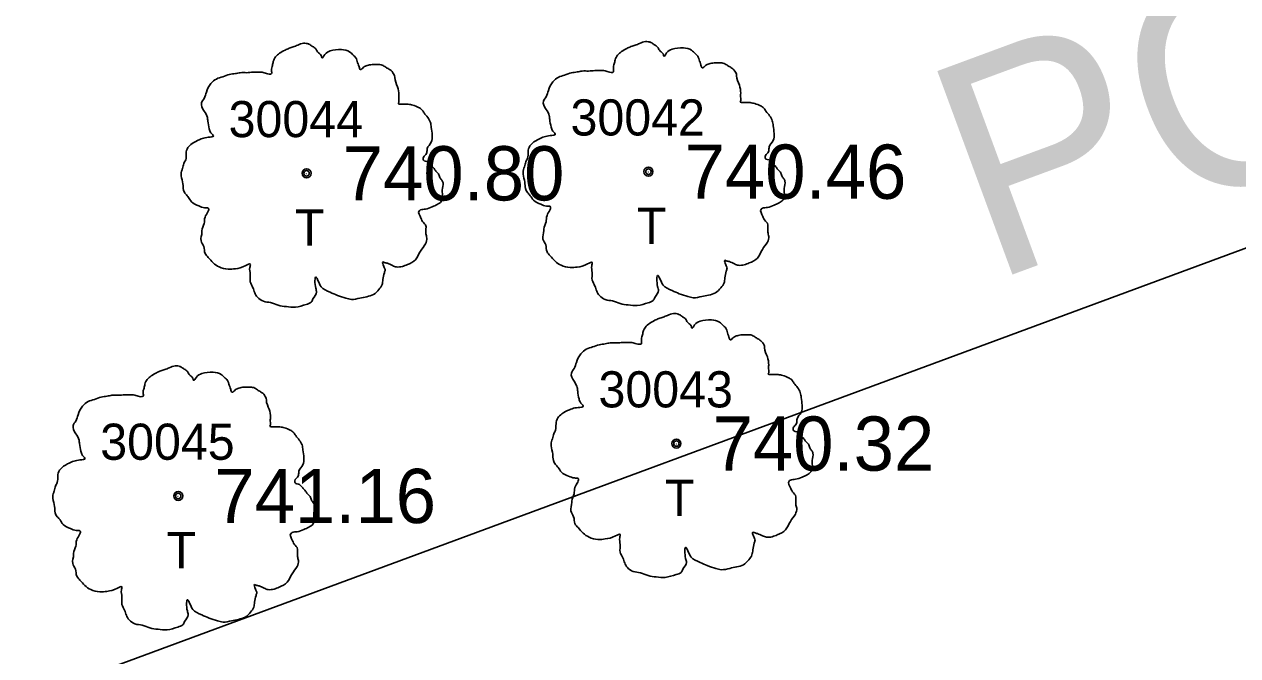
# Model space of a CAD drawing. Extents: x 1375131 to 1378678, y 999028 to 1004053.
# Drawn here: x 1376836.45 to 1376870.03, y 1002752.76 to 1002770.23 of the extents above; entities that cross this region are included whole.
import ezdxf

# ---------------------------------------------------------------- set-up
doc = ezdxf.new("R2010")
doc.units = 0
for name, color, linetype in [('RD_EX_TX_VEG_ELEV', 7, 'Continuous'), ('RD_EX_VEG', 7, 'Continuous'), ('RD_EX_VEG_txCode', 7, 'Continuous'), ('RD_HC_Data', 7, 'Continuous'), ('RD_SMD_Locator', 7, 'Continuous')]:
    doc.layers.add(name, color=color, linetype=linetype)

msp = doc.modelspace()

# ---------------------------------------------------------------- linework, layer by layer
at = {"layer": 'RD_EX_VEG'}
for centre, radius in [((1376844.264, 1002766.106), 0.125), ((1376844.258, 1002766.097), 0.00005), ((1376853.726, 1002766.152), 0.125), ((1376853.72, 1002766.143), 0.00005), ((1376854.5, 1002758.631), 0.125), ((1376854.494, 1002758.622), 0.00005), ((1376840.712, 1002757.182), 0.125), ((1376840.706, 1002757.173), 0.00005)]:
    msp.add_circle(centre, radius, dxfattribs=at)
for points in [[(1376853.792, 1002769.736), (1376853.642, 1002769.748), (1376853.48, 1002769.698), (1376853.355, 1002769.648), (1376853.242, 1002769.611), (1376853.13, 1002769.561), (1376852.98, 1002769.473), (1376852.867, 1002769.373), (1376852.805, 1002769.248), (1376852.78, 1002769.136), (1376852.755, 1002768.998), (1376852.755, 1002768.911), (1376852.692, 1002768.898), (1376852.617, 1002768.911), (1376852.493, 1002768.948), (1376852.368, 1002768.948), (1376852.243, 1002768.948), (1376852.068, 1002768.936), (1376851.893, 1002768.936), (1376851.755, 1002768.911), (1376851.593, 1002768.886), (1376851.406, 1002768.824), (1376851.231, 1002768.761), (1376851.081, 1002768.636), (1376850.956, 1002768.399), (1376850.893, 1002768.224), (1376850.818, 1002768.099), (1376850.893, 1002767.874), (1376850.981, 1002767.699), (1376850.993, 1002767.599), (1376851.031, 1002767.387), (1376851.081, 1002767.274), (1376851.143, 1002767.174), (1376851.106, 1002767.162), (1376850.918, 1002767.137), (1376850.768, 1002767.087), (1376850.556, 1002766.974), (1376850.443, 1002766.862), (1376850.393, 1002766.699), (1376850.381, 1002766.525), (1376850.331, 1002766.425), (1376850.294, 1002766.287), (1376850.281, 1002766.25), (1376850.256, 1002766.087), (1376850.306, 1002765.862), (1376850.319, 1002765.687), (1376850.381, 1002765.575), (1376850.456, 1002765.488), (1376850.543, 1002765.363), (1376850.743, 1002765.25), (1376850.906, 1002765.2), (1376851.006, 1002765.188), (1376850.918, 1002764.938), (1376850.893, 1002764.763), (1376850.831, 1002764.563), (1376850.831, 1002764.525), (1376850.806, 1002764.288), (1376850.881, 1002764.126), (1376850.918, 1002763.938), (1376851.006, 1002763.826), (1376851.143, 1002763.676), (1376851.306, 1002763.563), (1376851.555, 1002763.501), (1376851.755, 1002763.513), (1376852.043, 1002763.601), (1376852.168, 1002763.638), (1376852.155, 1002763.551), (1376852.168, 1002763.363), (1376852.168, 1002763.151), (1376852.243, 1002762.989), (1376852.293, 1002762.851), (1376852.368, 1002762.726), (1376852.53, 1002762.614), (1376852.73, 1002762.576), (1376852.942, 1002762.501), (1376853.167, 1002762.464), (1376853.417, 1002762.451), (1376853.717, 1002762.526), (1376853.854, 1002762.589), (1376853.904, 1002762.676), (1376854.004, 1002762.864), (1376853.979, 1002762.976), (1376853.992, 1002763.276), (1376854.042, 1002763.188), (1376854.129, 1002763.014), (1376854.379, 1002762.864), (1376854.579, 1002762.776), (1376854.817, 1002762.701), (1376854.966, 1002762.664), (1376855.204, 1002762.701), (1376855.391, 1002762.739), (1376855.579, 1002762.801), (1376855.729, 1002762.939), (1376855.816, 1002763.076), (1376855.841, 1002763.213), (1376855.879, 1002763.401), (1376855.904, 1002763.488)], [(1376844.33, 1002769.69), (1376844.18, 1002769.702), (1376844.018, 1002769.652), (1376843.893, 1002769.602), (1376843.78, 1002769.565), (1376843.668, 1002769.515), (1376843.518, 1002769.427), (1376843.405, 1002769.327), (1376843.343, 1002769.202), (1376843.318, 1002769.09), (1376843.293, 1002768.952), (1376843.293, 1002768.865), (1376843.23, 1002768.852), (1376843.155, 1002768.865), (1376843.031, 1002768.902), (1376842.906, 1002768.902), (1376842.781, 1002768.902), (1376842.606, 1002768.89), (1376842.431, 1002768.89), (1376842.293, 1002768.865), (1376842.131, 1002768.84), (1376841.944, 1002768.778), (1376841.769, 1002768.715), (1376841.619, 1002768.59), (1376841.494, 1002768.353), (1376841.431, 1002768.178), (1376841.356, 1002768.053), (1376841.431, 1002767.828), (1376841.519, 1002767.653), (1376841.531, 1002767.553), (1376841.569, 1002767.341), (1376841.619, 1002767.228), (1376841.681, 1002767.128), (1376841.644, 1002767.116), (1376841.456, 1002767.091), (1376841.306, 1002767.041), (1376841.094, 1002766.928), (1376840.981, 1002766.816), (1376840.931, 1002766.653), (1376840.919, 1002766.479), (1376840.869, 1002766.379), (1376840.832, 1002766.241), (1376840.819, 1002766.204), (1376840.794, 1002766.041), (1376840.844, 1002765.816), (1376840.857, 1002765.641), (1376840.919, 1002765.529), (1376840.994, 1002765.442), (1376841.081, 1002765.317), (1376841.281, 1002765.204), (1376841.444, 1002765.154), (1376841.544, 1002765.142), (1376841.456, 1002764.892), (1376841.431, 1002764.717), (1376841.369, 1002764.517), (1376841.369, 1002764.479), (1376841.344, 1002764.242), (1376841.419, 1002764.08), (1376841.456, 1002763.892), (1376841.544, 1002763.78), (1376841.681, 1002763.63), (1376841.844, 1002763.517), (1376842.093, 1002763.455), (1376842.293, 1002763.467), (1376842.581, 1002763.555), (1376842.706, 1002763.592), (1376842.693, 1002763.505), (1376842.706, 1002763.317), (1376842.706, 1002763.105), (1376842.781, 1002762.943), (1376842.831, 1002762.805), (1376842.906, 1002762.68), (1376843.068, 1002762.568), (1376843.268, 1002762.53), (1376843.48, 1002762.455), (1376843.705, 1002762.418), (1376843.955, 1002762.405), (1376844.255, 1002762.48), (1376844.392, 1002762.543), (1376844.442, 1002762.63), (1376844.542, 1002762.818), (1376844.517, 1002762.93), (1376844.53, 1002763.23), (1376844.58, 1002763.142), (1376844.667, 1002762.968), (1376844.917, 1002762.818), (1376845.117, 1002762.73), (1376845.355, 1002762.655), (1376845.504, 1002762.618), (1376845.742, 1002762.655), (1376845.929, 1002762.693), (1376846.117, 1002762.755), (1376846.267, 1002762.893), (1376846.354, 1002763.03), (1376846.379, 1002763.167), (1376846.417, 1002763.355), (1376846.442, 1002763.442)], [(1376846.442, 1002763.442), (1376846.404, 1002763.53), (1376846.379, 1002763.655), (1376846.417, 1002763.642), (1376846.504, 1002763.617), (1376846.641, 1002763.555), (1376846.754, 1002763.517), (1376846.916, 1002763.53), (1376847.054, 1002763.58), (1376847.279, 1002763.717), (1376847.416, 1002763.955), (1376847.554, 1002764.155), (1376847.591, 1002764.317), (1376847.566, 1002764.429), (1376847.554, 1002764.679), (1376847.454, 1002764.804), (1376847.429, 1002764.867), (1376847.379, 1002765.067), (1376847.416, 1002765.092), (1376847.554, 1002765.117), (1376847.741, 1002765.179), (1376847.878, 1002765.242), (1376847.991, 1002765.329), (1376848.028, 1002765.442), (1376848.016, 1002765.641), (1376848.041, 1002765.841), (1376848.003, 1002765.916), (1376847.953, 1002765.991), (1376847.916, 1002766.091), (1376847.841, 1002766.166), (1376847.791, 1002766.241), (1376847.741, 1002766.291), (1376847.679, 1002766.366), (1376847.591, 1002766.429), (1376847.516, 1002766.454), (1376847.491, 1002766.529), (1376847.566, 1002766.628), (1376847.591, 1002766.678), (1376847.604, 1002766.791), (1376847.716, 1002766.966), (1376847.741, 1002767.166), (1376847.716, 1002767.378), (1376847.691, 1002767.516), (1376847.616, 1002767.653), (1376847.516, 1002767.778), (1376847.454, 1002767.865), (1376847.366, 1002767.928), (1376847.204, 1002767.99), (1376847.079, 1002768.015), (1376846.904, 1002768.015), (1376846.804, 1002768.04), (1376846.816, 1002768.065), (1376846.816, 1002768.14), (1376846.816, 1002768.278), (1376846.779, 1002768.503), (1376846.704, 1002768.753), (1376846.704, 1002768.765), (1376846.654, 1002768.89), (1376846.542, 1002768.99), (1376846.454, 1002769.04), (1376846.354, 1002769.102), (1376846.229, 1002769.115), (1376846.079, 1002769.115), (1376845.942, 1002769.09), (1376845.842, 1002769.04), (1376845.754, 1002768.977), (1376845.717, 1002769.052), (1376845.667, 1002769.202), (1376845.642, 1002769.277), (1376845.567, 1002769.365), (1376845.455, 1002769.465), (1376845.23, 1002769.527), (1376844.917, 1002769.49), (1376844.767, 1002769.39), (1376844.692, 1002769.302), (1376844.667, 1002769.365), (1376844.567, 1002769.465), (1376844.517, 1002769.552), (1376844.43, 1002769.615), (1376844.355, 1002769.665), (1376844.305, 1002769.69)], [(1376855.904, 1002763.488), (1376855.866, 1002763.576), (1376855.841, 1002763.701), (1376855.879, 1002763.688), (1376855.966, 1002763.663), (1376856.103, 1002763.601), (1376856.216, 1002763.563), (1376856.378, 1002763.576), (1376856.516, 1002763.626), (1376856.741, 1002763.763), (1376856.878, 1002764.001), (1376857.016, 1002764.201), (1376857.053, 1002764.363), (1376857.028, 1002764.475), (1376857.016, 1002764.725), (1376856.916, 1002764.85), (1376856.891, 1002764.913), (1376856.841, 1002765.113), (1376856.878, 1002765.138), (1376857.016, 1002765.163), (1376857.203, 1002765.225), (1376857.34, 1002765.288), (1376857.453, 1002765.375), (1376857.49, 1002765.488), (1376857.478, 1002765.687), (1376857.503, 1002765.887), (1376857.465, 1002765.962), (1376857.415, 1002766.037), (1376857.378, 1002766.137), (1376857.303, 1002766.212), (1376857.253, 1002766.287), (1376857.203, 1002766.337), (1376857.141, 1002766.412), (1376857.053, 1002766.475), (1376856.978, 1002766.5), (1376856.953, 1002766.575), (1376857.028, 1002766.674), (1376857.053, 1002766.724), (1376857.066, 1002766.837), (1376857.178, 1002767.012), (1376857.203, 1002767.212), (1376857.178, 1002767.424), (1376857.153, 1002767.562), (1376857.078, 1002767.699), (1376856.978, 1002767.824), (1376856.916, 1002767.911), (1376856.828, 1002767.974), (1376856.666, 1002768.036), (1376856.541, 1002768.061), (1376856.366, 1002768.061), (1376856.266, 1002768.086), (1376856.278, 1002768.111), (1376856.278, 1002768.186), (1376856.278, 1002768.324), (1376856.241, 1002768.549), (1376856.166, 1002768.799), (1376856.166, 1002768.811), (1376856.116, 1002768.936), (1376856.004, 1002769.036), (1376855.916, 1002769.086), (1376855.816, 1002769.148), (1376855.691, 1002769.161), (1376855.541, 1002769.161), (1376855.404, 1002769.136), (1376855.304, 1002769.086), (1376855.216, 1002769.023), (1376855.179, 1002769.098), (1376855.129, 1002769.248), (1376855.104, 1002769.323), (1376855.029, 1002769.411), (1376854.917, 1002769.511), (1376854.692, 1002769.573), (1376854.379, 1002769.536), (1376854.229, 1002769.436), (1376854.154, 1002769.348), (1376854.129, 1002769.411), (1376854.029, 1002769.511), (1376853.979, 1002769.598), (1376853.892, 1002769.661), (1376853.817, 1002769.711), (1376853.767, 1002769.736)], [(1376854.566, 1002762.215), (1376854.416, 1002762.227), (1376854.254, 1002762.177), (1376854.129, 1002762.127), (1376854.016, 1002762.09), (1376853.904, 1002762.04), (1376853.754, 1002761.952), (1376853.641, 1002761.852), (1376853.579, 1002761.727), (1376853.554, 1002761.615), (1376853.529, 1002761.477), (1376853.529, 1002761.39), (1376853.466, 1002761.377), (1376853.391, 1002761.39), (1376853.267, 1002761.427), (1376853.142, 1002761.427), (1376853.017, 1002761.427), (1376852.842, 1002761.415), (1376852.667, 1002761.415), (1376852.529, 1002761.39), (1376852.367, 1002761.365), (1376852.18, 1002761.303), (1376852.005, 1002761.24), (1376851.855, 1002761.115), (1376851.73, 1002760.878), (1376851.667, 1002760.703), (1376851.592, 1002760.578), (1376851.667, 1002760.353), (1376851.755, 1002760.178), (1376851.767, 1002760.078), (1376851.805, 1002759.866), (1376851.855, 1002759.753), (1376851.917, 1002759.653), (1376851.88, 1002759.641), (1376851.692, 1002759.616), (1376851.542, 1002759.566), (1376851.33, 1002759.453), (1376851.217, 1002759.341), (1376851.167, 1002759.178), (1376851.155, 1002759.004), (1376851.105, 1002758.904), (1376851.068, 1002758.766), (1376851.055, 1002758.729), (1376851.03, 1002758.566), (1376851.08, 1002758.341), (1376851.093, 1002758.166), (1376851.155, 1002758.054), (1376851.23, 1002757.967), (1376851.317, 1002757.842), (1376851.517, 1002757.729), (1376851.68, 1002757.679), (1376851.78, 1002757.667), (1376851.692, 1002757.417), (1376851.667, 1002757.242), (1376851.605, 1002757.042), (1376851.605, 1002757.004), (1376851.58, 1002756.767), (1376851.655, 1002756.605), (1376851.692, 1002756.417), (1376851.78, 1002756.305), (1376851.917, 1002756.155), (1376852.08, 1002756.042), (1376852.329, 1002755.98), (1376852.529, 1002755.992), (1376852.817, 1002756.08), (1376852.942, 1002756.117), (1376852.929, 1002756.03), (1376852.942, 1002755.842), (1376852.942, 1002755.63), (1376853.017, 1002755.468), (1376853.067, 1002755.33), (1376853.142, 1002755.205), (1376853.304, 1002755.093), (1376853.504, 1002755.055), (1376853.716, 1002754.98), (1376853.941, 1002754.943), (1376854.191, 1002754.93), (1376854.491, 1002755.005), (1376854.628, 1002755.068), (1376854.678, 1002755.155), (1376854.778, 1002755.343), (1376854.753, 1002755.455), (1376854.766, 1002755.755), (1376854.816, 1002755.667), (1376854.903, 1002755.493), (1376855.153, 1002755.343), (1376855.353, 1002755.255), (1376855.591, 1002755.18), (1376855.74, 1002755.143), (1376855.978, 1002755.18), (1376856.165, 1002755.218), (1376856.353, 1002755.28), (1376856.503, 1002755.418), (1376856.59, 1002755.555), (1376856.615, 1002755.692), (1376856.653, 1002755.88), (1376856.678, 1002755.967)], [(1376856.678, 1002755.967), (1376856.64, 1002756.055), (1376856.615, 1002756.18), (1376856.653, 1002756.167), (1376856.74, 1002756.142), (1376856.877, 1002756.08), (1376856.99, 1002756.042), (1376857.152, 1002756.055), (1376857.29, 1002756.105), (1376857.515, 1002756.242), (1376857.652, 1002756.48), (1376857.79, 1002756.68), (1376857.827, 1002756.842), (1376857.802, 1002756.954), (1376857.79, 1002757.204), (1376857.69, 1002757.329), (1376857.665, 1002757.392), (1376857.615, 1002757.592), (1376857.652, 1002757.617), (1376857.79, 1002757.642), (1376857.977, 1002757.704), (1376858.114, 1002757.767), (1376858.227, 1002757.854), (1376858.264, 1002757.967), (1376858.252, 1002758.166), (1376858.277, 1002758.366), (1376858.239, 1002758.441), (1376858.189, 1002758.516), (1376858.152, 1002758.616), (1376858.077, 1002758.691), (1376858.027, 1002758.766), (1376857.977, 1002758.816), (1376857.915, 1002758.891), (1376857.827, 1002758.954), (1376857.752, 1002758.979), (1376857.727, 1002759.054), (1376857.802, 1002759.153), (1376857.827, 1002759.203), (1376857.84, 1002759.316), (1376857.952, 1002759.491), (1376857.977, 1002759.691), (1376857.952, 1002759.903), (1376857.927, 1002760.041), (1376857.852, 1002760.178), (1376857.752, 1002760.303), (1376857.69, 1002760.39), (1376857.602, 1002760.453), (1376857.44, 1002760.515), (1376857.315, 1002760.54), (1376857.14, 1002760.54), (1376857.04, 1002760.565), (1376857.052, 1002760.59), (1376857.052, 1002760.665), (1376857.052, 1002760.803), (1376857.015, 1002761.028), (1376856.94, 1002761.278), (1376856.94, 1002761.29), (1376856.89, 1002761.415), (1376856.778, 1002761.515), (1376856.69, 1002761.565), (1376856.59, 1002761.627), (1376856.465, 1002761.64), (1376856.315, 1002761.64), (1376856.178, 1002761.615), (1376856.078, 1002761.565), (1376855.99, 1002761.502), (1376855.953, 1002761.577), (1376855.903, 1002761.727), (1376855.878, 1002761.802), (1376855.803, 1002761.89), (1376855.691, 1002761.99), (1376855.466, 1002762.052), (1376855.153, 1002762.015), (1376855.003, 1002761.915), (1376854.928, 1002761.827), (1376854.903, 1002761.89), (1376854.803, 1002761.99), (1376854.753, 1002762.077), (1376854.666, 1002762.14), (1376854.591, 1002762.19), (1376854.541, 1002762.215)], [(1376840.778, 1002760.766), (1376840.628, 1002760.778), (1376840.466, 1002760.728), (1376840.341, 1002760.678), (1376840.228, 1002760.641), (1376840.116, 1002760.591), (1376839.966, 1002760.503), (1376839.853, 1002760.403), (1376839.791, 1002760.278), (1376839.766, 1002760.166), (1376839.741, 1002760.028), (1376839.741, 1002759.941), (1376839.678, 1002759.928), (1376839.603, 1002759.941), (1376839.479, 1002759.978), (1376839.354, 1002759.978), (1376839.229, 1002759.978), (1376839.054, 1002759.966), (1376838.879, 1002759.966), (1376838.741, 1002759.941), (1376838.579, 1002759.916), (1376838.392, 1002759.854), (1376838.217, 1002759.791), (1376838.067, 1002759.666), (1376837.942, 1002759.429), (1376837.879, 1002759.254), (1376837.804, 1002759.129), (1376837.879, 1002758.904), (1376837.967, 1002758.729), (1376837.979, 1002758.629), (1376838.017, 1002758.417), (1376838.067, 1002758.304), (1376838.129, 1002758.204), (1376838.092, 1002758.192), (1376837.904, 1002758.167), (1376837.754, 1002758.117), (1376837.542, 1002758.004), (1376837.429, 1002757.892), (1376837.379, 1002757.729), (1376837.367, 1002757.555), (1376837.317, 1002757.455), (1376837.28, 1002757.317), (1376837.267, 1002757.28), (1376837.242, 1002757.117), (1376837.292, 1002756.892), (1376837.305, 1002756.717), (1376837.367, 1002756.605), (1376837.442, 1002756.518), (1376837.529, 1002756.393), (1376837.729, 1002756.28), (1376837.892, 1002756.23), (1376837.992, 1002756.218), (1376837.904, 1002755.968), (1376837.879, 1002755.793), (1376837.817, 1002755.593), (1376837.817, 1002755.555), (1376837.792, 1002755.318), (1376837.867, 1002755.156), (1376837.904, 1002754.968), (1376837.992, 1002754.856), (1376838.129, 1002754.706), (1376838.292, 1002754.593), (1376838.541, 1002754.531), (1376838.741, 1002754.543), (1376839.029, 1002754.631), (1376839.154, 1002754.668), (1376839.141, 1002754.581), (1376839.154, 1002754.393), (1376839.154, 1002754.181), (1376839.229, 1002754.019), (1376839.279, 1002753.881), (1376839.354, 1002753.756), (1376839.516, 1002753.644), (1376839.716, 1002753.606), (1376839.928, 1002753.531), (1376840.153, 1002753.494), (1376840.403, 1002753.481), (1376840.703, 1002753.556), (1376840.84, 1002753.619), (1376840.89, 1002753.706), (1376840.99, 1002753.894), (1376840.965, 1002754.006), (1376840.978, 1002754.306), (1376841.028, 1002754.218), (1376841.115, 1002754.044), (1376841.365, 1002753.894), (1376841.565, 1002753.806), (1376841.803, 1002753.731), (1376841.952, 1002753.694), (1376842.19, 1002753.731), (1376842.377, 1002753.769), (1376842.565, 1002753.831), (1376842.715, 1002753.969), (1376842.802, 1002754.106), (1376842.827, 1002754.243), (1376842.865, 1002754.431), (1376842.89, 1002754.518)], [(1376842.89, 1002754.518), (1376842.852, 1002754.606), (1376842.827, 1002754.731), (1376842.865, 1002754.718), (1376842.952, 1002754.693), (1376843.089, 1002754.631), (1376843.202, 1002754.593), (1376843.364, 1002754.606), (1376843.502, 1002754.656), (1376843.727, 1002754.793), (1376843.864, 1002755.031), (1376844.002, 1002755.231), (1376844.039, 1002755.393), (1376844.014, 1002755.505), (1376844.002, 1002755.755), (1376843.902, 1002755.88), (1376843.877, 1002755.943), (1376843.827, 1002756.143), (1376843.864, 1002756.168), (1376844.002, 1002756.193), (1376844.189, 1002756.255), (1376844.326, 1002756.318), (1376844.439, 1002756.405), (1376844.476, 1002756.518), (1376844.464, 1002756.717), (1376844.489, 1002756.917), (1376844.451, 1002756.992), (1376844.401, 1002757.067), (1376844.364, 1002757.167), (1376844.289, 1002757.242), (1376844.239, 1002757.317), (1376844.189, 1002757.367), (1376844.127, 1002757.442), (1376844.039, 1002757.505), (1376843.964, 1002757.53), (1376843.939, 1002757.605), (1376844.014, 1002757.704), (1376844.039, 1002757.754), (1376844.052, 1002757.867), (1376844.164, 1002758.042), (1376844.189, 1002758.242), (1376844.164, 1002758.454), (1376844.139, 1002758.592), (1376844.064, 1002758.729), (1376843.964, 1002758.854), (1376843.902, 1002758.941), (1376843.814, 1002759.004), (1376843.652, 1002759.066), (1376843.527, 1002759.091), (1376843.352, 1002759.091), (1376843.252, 1002759.116), (1376843.264, 1002759.141), (1376843.264, 1002759.216), (1376843.264, 1002759.354), (1376843.227, 1002759.579), (1376843.152, 1002759.829), (1376843.152, 1002759.841), (1376843.102, 1002759.966), (1376842.99, 1002760.066), (1376842.902, 1002760.116), (1376842.802, 1002760.178), (1376842.677, 1002760.191), (1376842.527, 1002760.191), (1376842.39, 1002760.166), (1376842.29, 1002760.116), (1376842.202, 1002760.053), (1376842.165, 1002760.128), (1376842.115, 1002760.278), (1376842.09, 1002760.353), (1376842.015, 1002760.441), (1376841.903, 1002760.541), (1376841.678, 1002760.603), (1376841.365, 1002760.566), (1376841.215, 1002760.466), (1376841.14, 1002760.378), (1376841.115, 1002760.441), (1376841.015, 1002760.541), (1376840.965, 1002760.628), (1376840.878, 1002760.691), (1376840.803, 1002760.741), (1376840.753, 1002760.766)]]:
    msp.add_spline(points, degree=3, dxfattribs=at)
at = {"layer": 'RD_HC_Data'}
msp.add_line((1376778.262, 1002730.065), (1376911.622, 1002779.317), dxfattribs=at)
at = {"layer": 'RD_SMD_Locator'}
for centre in [(1376844.264, 1002766.106), (1376853.726, 1002766.152), (1376854.5, 1002758.631), (1376840.712, 1002757.182)]:
    msp.add_circle(centre, 0.075, dxfattribs=at)

# ---------------------------------------------------------------- texts
at = {"layer": 'RD_EX_TX_VEG_ELEV'}
for s, p in [('740.80', (1376845.264, 1002765.356)), ('740.46', (1376854.726, 1002765.402)), ('740.32', (1376855.5, 1002757.881)), ('741.16', (1376841.712, 1002756.432))]:
    msp.add_text(s, height=1.5, dxfattribs=at).set_placement(p)
at = {"layer": 'RD_EX_VEG_txCode'}
for s, p in [('30044', (1376842.107, 1002767.106)), ('30042', (1376851.569, 1002767.152)), ('T', (1376843.941, 1002764.106)), ('T', (1376853.403, 1002764.152)), ('30043', (1376852.343, 1002759.631)), ('30045', (1376838.555, 1002758.182)), ('T', (1376854.177, 1002756.631)), ('T', (1376840.389, 1002755.182))]:
    msp.add_text(s, height=1, dxfattribs=at).set_placement(p)
at = {"layer": 'RD_HC_Data'}
msp.add_text('PC=34+16.40', height=6, rotation=20.27, dxfattribs=at).set_placement((1376863.181, 1002763.078))

doc.saveas('drawing.dxf')
